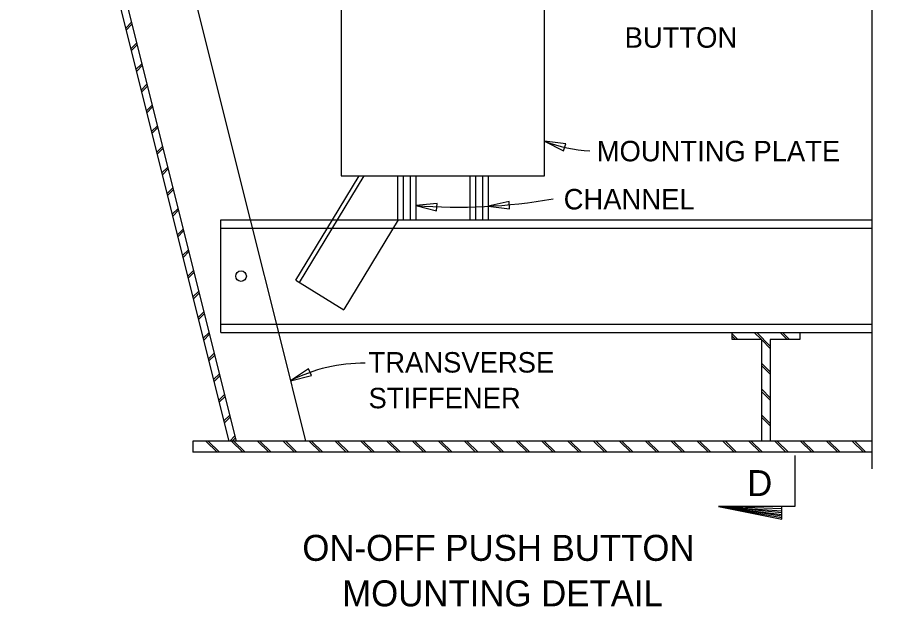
# Model space of a CAD drawing. Extents: x 927736.2 to 927809.6, y 636703.6 to 636757.7.
# Drawn here: x 927758.43 to 927774.19, y 636710.59 to 636721.33 of the extents above; entities that cross this region are included whole.
import ezdxf

# ---------------------------------------------------------------- set-up
doc = ezdxf.new("R2010")
doc.units = 0
for name, color, linetype in [('Default', 7, 'Continuous'), ('DimLines_dp', 7, 'Continuous'), ('Miscellaneous1', 7, 'Continuous'), ('Miscellaneous3', 7, 'Continuous')]:
    doc.layers.add(name, color=color, linetype=linetype)

msp = doc.modelspace()

# ---------------------------------------------------------------- linework, layer by layer
at = {"layer": 'DimLines_dp'}
for p, q in [((927772.357, 636712.378), (927771.201, 636712.421)), ((927771.201, 636712.421), (927772.357, 636712.341)), ((927772.357, 636712.307), (927771.201, 636712.421)), ((927771.201, 636712.421), (927772.357, 636712.273)), ((927772.357, 636712.242), (927771.201, 636712.421)), ((927771.201, 636712.421), (927772.357, 636712.218))]:
    msp.add_line(p, q, dxfattribs=at)
for points in [[(927774, 636713.104), (927774, 636722.378), (927773.809, 636722.378), (927774, 636722.461), (927774.191, 636722.544), (927774, 636722.544), (927774, 636731.999)], [(927772.589, 636713.346), (927772.589, 636712.421), (927771.201, 636712.421), (927772.357, 636712.19), (927772.357, 636712.421)]]:
    msp.add_lwpolyline(points, dxfattribs=at)
for points in [[(927768.032, 636719.079), (927768.38, 636718.901), (927768.419, 636719.026)], [(927767.01, 636717.89), (927767.398, 636717.846), (927767.391, 636717.977)], [(927765.688, 636717.904), (927766.067, 636717.809), (927766.077, 636717.939)], [(927763.409, 636714.711), (927763.788, 636714.806), (927763.736, 636714.926)]]:
    msp.add_lwpolyline(points, close=True, dxfattribs=at)
for centre, radius, start, end in [((927768.996, 636721.566), 2.667, 248.8193, 267.0903), ((927766.454, 636727.853), 9.978, 265.6012, 280.0186)]:
    msp.add_arc(centre, radius, start, end, dxfattribs=at)
msp.add_ellipse((927764.747, 636711.794), major_axis=(-0.021, -3.238), ratio=0.953713, start_param=3.141601, end_param=3.59647, dxfattribs=at)
at = {"layer": 'Miscellaneous1'}
for p, q in [((927765.354, 636718.446), (927765.354, 636717.646)), ((927765.457, 636718.446), (927765.457, 636717.646)), ((927765.586, 636718.446), (927765.586, 636717.646)), ((927765.688, 636718.446), (927765.688, 636717.646)), ((927766.676, 636718.446), (927766.676, 636717.646)), ((927766.778, 636718.446), (927766.778, 636717.646)), ((927766.907, 636718.446), (927766.907, 636717.646)), ((927767.01, 636718.446), (927767.01, 636717.646))]:
    msp.add_line(p, q, dxfattribs=at)
at = {"layer": 'Miscellaneous3'}
for p, q in [((927758.434, 636729.029), (927762.288, 636713.612)), ((927758.566, 636729.029), (927762.42, 636713.612)), ((927760.241, 636727.384), (927762.676, 636717.646)), ((927760.407, 636721.137), (927760.513, 636721.243)), ((927760.416, 636721.102), (927760.522, 636721.208)), ((927760.501, 636720.76), (927760.607, 636720.866)), ((927760.51, 636720.725), (927760.616, 636720.831)), ((927760.595, 636720.383), (927760.701, 636720.489)), ((927760.604, 636720.349), (927760.71, 636720.454)), ((927760.689, 636720.007), (927760.795, 636720.113)), ((927760.698, 636719.972), (927760.804, 636720.078)), ((927760.784, 636719.63), (927760.89, 636719.736)), ((927760.792, 636719.595), (927760.898, 636719.701)), ((927760.878, 636719.253), (927760.984, 636719.359)), ((927760.886, 636719.218), (927760.992, 636719.324)), ((927760.972, 636718.876), (927761.078, 636718.982)), ((927760.981, 636718.842), (927761.087, 636718.948)), ((927761.066, 636718.5), (927761.172, 636718.606)), ((927761.075, 636718.465), (927761.181, 636718.571)), ((927763.572, 636716.504), (927764.747, 636718.446)), ((927764.173, 636717.646), (927764.657, 636718.446)), ((927761.16, 636718.123), (927761.266, 636718.229)), ((927761.169, 636718.088), (927761.275, 636718.194)), ((927761.254, 636717.746), (927761.36, 636717.852)), ((927761.263, 636717.711), (927761.369, 636717.817)), ((927762.138, 636717.646), (927774, 636717.646)), ((927762.138, 636715.591), (927762.138, 636717.646)), ((927762.675, 636717.646), (927763.189, 636715.591)), ((927763.506, 636716.544), (927764.173, 636717.646)), ((927764.383, 636716.007), (927765.374, 636717.646)), ((927761.349, 636717.369), (927761.455, 636717.475)), ((927761.357, 636717.335), (927761.463, 636717.441)), ((927762.138, 636717.492), (927774, 636717.492)), ((927761.443, 636716.993), (927761.549, 636717.099)), ((927761.452, 636716.958), (927761.558, 636717.064)), ((927761.537, 636716.616), (927761.643, 636716.722)), ((927761.546, 636716.581), (927761.652, 636716.687)), ((927763.506, 636716.544), (927764.379, 636716.002)), ((927761.631, 636716.239), (927761.737, 636716.345)), ((927761.64, 636716.204), (927761.746, 636716.31)), ((927761.725, 636715.862), (927761.831, 636715.968)), ((927761.734, 636715.828), (927761.84, 636715.934)), ((927762.138, 636715.745), (927774, 636715.745)), ((927761.82, 636715.486), (927761.926, 636715.592)), ((927761.828, 636715.451), (927761.934, 636715.557)), ((927762.138, 636715.591), (927774, 636715.591)), ((927763.189, 636715.591), (927763.684, 636713.612)), ((927771.555, 636715.462), (927771.45, 636715.567)), ((927771.511, 636715.462), (927771.45, 636715.523)), ((927771.982, 636715.462), (927771.853, 636715.591)), ((927772.144, 636715.344), (927771.897, 636715.591)), ((927772.144, 636715.3), (927771.99, 636715.454)), ((927772.453, 636715.462), (927772.324, 636715.591)), ((927772.496, 636715.462), (927772.368, 636715.591)), ((927761.914, 636715.109), (927762.02, 636715.215)), ((927761.923, 636715.074), (927762.028, 636715.18)), ((927772.144, 636714.873), (927771.99, 636715.027)), ((927772.144, 636714.829), (927771.99, 636714.983)), ((927762.008, 636714.732), (927762.114, 636714.838)), ((927762.017, 636714.697), (927762.123, 636714.803)), ((927772.144, 636714.402), (927771.99, 636714.556)), ((927772.144, 636714.358), (927771.99, 636714.512)), ((927762.102, 636714.355), (927762.208, 636714.461)), ((927762.111, 636714.321), (927762.217, 636714.427)), ((927762.196, 636713.979), (927762.302, 636714.085)), ((927762.205, 636713.944), (927762.311, 636714.05)), ((927772.144, 636713.931), (927771.99, 636714.085)), ((927772.144, 636713.887), (927771.99, 636714.041)), ((927763.433, 636713.612), (927761.631, 636713.612)), ((927761.631, 636713.612), (927761.631, 636713.407)), ((927761.631, 636713.612), (927761.631, 636713.407)), ((927762.07, 636713.407), (927761.864, 636713.612)), ((927762.113, 636713.407), (927761.908, 636713.612)), ((927762.301, 636713.612), (927762.397, 636713.708)), ((927762.541, 636713.407), (927762.335, 636713.612)), ((927762.344, 636713.612), (927762.405, 636713.673)), ((927762.584, 636713.407), (927762.379, 636713.612)), ((927763.012, 636713.407), (927762.806, 636713.612)), ((927763.055, 636713.407), (927762.85, 636713.612)), ((927763.483, 636713.407), (927763.277, 636713.612)), ((927763.526, 636713.407), (927763.321, 636713.612)), ((927772.067, 636713.612), (927763.434, 636713.612)), ((927763.953, 636713.407), (927763.748, 636713.612)), ((927763.997, 636713.407), (927763.792, 636713.612)), ((927764.424, 636713.407), (927764.219, 636713.612)), ((927764.468, 636713.407), (927764.263, 636713.612)), ((927764.895, 636713.407), (927764.69, 636713.612)), ((927764.939, 636713.407), (927764.734, 636713.612)), ((927765.366, 636713.407), (927765.161, 636713.612)), ((927765.41, 636713.407), (927765.204, 636713.612)), ((927765.837, 636713.407), (927765.632, 636713.612)), ((927765.881, 636713.407), (927765.675, 636713.612)), ((927766.308, 636713.407), (927766.103, 636713.612)), ((927766.352, 636713.407), (927766.146, 636713.612)), ((927766.779, 636713.407), (927766.574, 636713.612)), ((927766.823, 636713.407), (927766.617, 636713.612)), ((927767.25, 636713.407), (927767.045, 636713.612)), ((927767.294, 636713.407), (927767.088, 636713.612)), ((927767.721, 636713.407), (927767.516, 636713.612)), ((927767.765, 636713.407), (927767.559, 636713.612)), ((927768.192, 636713.407), (927767.986, 636713.612)), ((927768.235, 636713.407), (927768.03, 636713.612)), ((927768.663, 636713.407), (927768.457, 636713.612)), ((927768.706, 636713.407), (927768.501, 636713.612)), ((927769.134, 636713.407), (927768.928, 636713.612)), ((927769.177, 636713.407), (927768.972, 636713.612)), ((927769.605, 636713.407), (927769.399, 636713.612)), ((927769.648, 636713.407), (927769.443, 636713.612)), ((927770.076, 636713.407), (927769.87, 636713.612)), ((927770.119, 636713.407), (927769.914, 636713.612)), ((927770.547, 636713.407), (927770.341, 636713.612)), ((927770.59, 636713.407), (927770.385, 636713.612)), ((927771.017, 636713.407), (927770.812, 636713.612)), ((927771.061, 636713.407), (927770.856, 636713.612)), ((927771.488, 636713.407), (927771.283, 636713.612)), ((927771.532, 636713.407), (927771.327, 636713.612)), ((927771.959, 636713.407), (927771.754, 636713.612)), ((927772.003, 636713.407), (927771.798, 636713.612)), ((927771.992, 636713.612), (927771.99, 636713.614)), ((927774, 636713.612), (927772.067, 636713.612)), ((927772.43, 636713.407), (927772.225, 636713.612)), ((927772.474, 636713.407), (927772.268, 636713.612)), ((927772.901, 636713.407), (927772.696, 636713.612)), ((927772.945, 636713.407), (927772.739, 636713.612)), ((927773.372, 636713.407), (927773.167, 636713.612)), ((927773.416, 636713.407), (927773.21, 636713.612)), ((927773.843, 636713.407), (927773.638, 636713.612)), ((927773.887, 636713.407), (927773.681, 636713.612)), ((927761.642, 636713.407), (927761.631, 636713.418)), ((927774, 636713.407), (927761.631, 636713.407))]:
    msp.add_line(p, q, dxfattribs=at)
for points in [[(927768.032, 636718.446), (927768.032, 636718.446), (927768.032, 636726.463), (927766.275, 636726.463)], [(927764.332, 636723.646), (927764.332, 636718.446), (927768.032, 636718.446)]]:
    msp.add_lwpolyline(points, dxfattribs=at)
msp.add_lwpolyline([(927771.99, 636713.612), (927771.99, 636715.462), (927771.45, 636715.462), (927771.45, 636715.591), (927772.683, 636715.591), (927772.683, 636715.462), (927772.144, 636715.462), (927772.144, 636713.612)], close=True, dxfattribs=at)
msp.add_circle((927762.508, 636716.618), 0.0964, dxfattribs=at)

# ---------------------------------------------------------------- texts
at = {"layer": 'Default'}
for s, p in [('ON-OFF PUSH BUTTON', (927763.624, 636711.429)), ('MOUNTING DETAIL', (927764.349, 636710.6))]:
    msp.add_text(s, height=0.4736, dxfattribs=at).set_placement(p)
at = {"layer": 'DimLines_dp'}
for s, height, p in [('BUTTON', 0.373, (927769.492, 636720.78)), ('MOUNTING PLATE', 0.37296, (927768.984, 636718.71)), ('CHANNEL', 0.373, (927768.383, 636717.833)), ('TRANSVERSE', 0.373, (927764.829, 636714.86)), ('STIFFENER', 0.373, (927764.829, 636714.209)), ('D', 0.474, (927771.723, 636712.609))]:
    msp.add_text(s, height=height, dxfattribs=at).set_placement(p)

doc.saveas('drawing.dxf')
